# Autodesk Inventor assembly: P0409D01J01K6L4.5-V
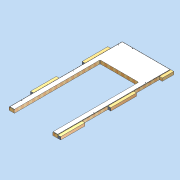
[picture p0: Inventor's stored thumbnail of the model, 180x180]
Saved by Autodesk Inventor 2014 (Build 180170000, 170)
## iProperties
Justset: False
Created: 2011-04
Part Number: P0409D01J01K6L4.5-V
Document SubType Name: Assembly
Designer: david.appleford
Description: 1w x 2.25w 01 Door Panel - 6 Locks 4.5 Lugs
Mass: 24000 g
Surface Area: 41498.3 cm^2
Volume: 109132 cm^3
Density: 0.219917 g/cm^3
Cost Center: £173.00
Title: 1w x 2.25w 01 Panel - 6 Locks 4.5 Lugs
Author: david.appleford
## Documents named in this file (5)
- C:\Documents and Settings\john.everitt\Local Settings\My Documents\Vault\Production MkII\Virtual Elements\Virtual Walls\Virtual Timber + MgO\P0409D01J01K6L4.5-V.iam
- C:\Documents and Settings\john.everitt\Local Settings\My Documents\Vault\Production MkII\VIRTUAL ELEMENTS\Virtual Lugs\Superceded Lugs\LA02C3V.ipt
- C:\Documents and Settings\john.everitt\Local Settings\My Documents\Vault\Production MkII\VIRTUAL ELEMENTS\Virtual Lugs\Superceded Lugs\LA02M3V.ipt
- C:\Documents and Settings\john.everitt\Local Settings\My Documents\Vault\Production MkII\VIRTUAL ELEMENTS\Virtual Lugs\Superceded Lugs\LA01C3V.ipt
- C:\Documents and Settings\john.everitt\Local Settings\My Documents\Vault\Production MkII\Virtual Elements\Virtual Walls\Virtual Timber + MgO\P0409D01J01K7-V.ipt
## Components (6 placed, 4 different names)
1. P0409D01J01K7-V:1 — Mate:1, Flush:1, Flush:2, Mate:5, Mate:6, Flush:9, Flush:10, Mate:7, Flush:11, Mate:14, Flush:12, Flush:13
2. LA02C3V:1 — Mate:1, Flush:1, Flush:2, Mate:9, Mate:13
3. LA02M3V:5 — Mate:6, Flush:9, Mate:12
4. LA02M3V:2 — Mate:5, Flush:10, Mate:12, Mate:13
5. LA02M3V:4 — Mate:7, Flush:11, Mate:9
6. LA01C3V:1 — Mate:14, Flush:12, Flush:13
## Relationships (15: Mate 8, Flush 7)
- Mate:1: P0409D01J01K7-V:1 ↔ LA02C3V:1
- Flush:1: P0409D01J01K7-V:1 ↔ LA02C3V:1
- Flush:2: P0409D01J01K7-V:1 ↔ LA02C3V:1
- Mate:5: P0409D01J01K7-V:1 ↔ LA02M3V:2
- Mate:6: P0409D01J01K7-V:1 ↔ LA02M3V:5
- Flush:9: P0409D01J01K7-V:1 ↔ LA02M3V:5
- Flush:10: P0409D01J01K7-V:1 ↔ LA02M3V:2
- Mate:7: P0409D01J01K7-V:1 ↔ LA02M3V:4
- Flush:11: P0409D01J01K7-V:1 ↔ LA02M3V:4
- Mate:9: LA02C3V:1 ↔ LA02M3V:4
- Mate:12: LA02M3V:5 ↔ LA02M3V:2
- Mate:13: LA02C3V:1 ↔ LA02M3V:2
- Mate:14: P0409D01J01K7-V:1 ↔ LA01C3V:1
- Flush:12: P0409D01J01K7-V:1 ↔ LA01C3V:1
- Flush:13: P0409D01J01K7-V:1 ↔ LA01C3V:1
## Named parameters: t = 1 mm, Cl = 2 mm
